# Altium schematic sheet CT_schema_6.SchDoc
size 373 x 245 mm
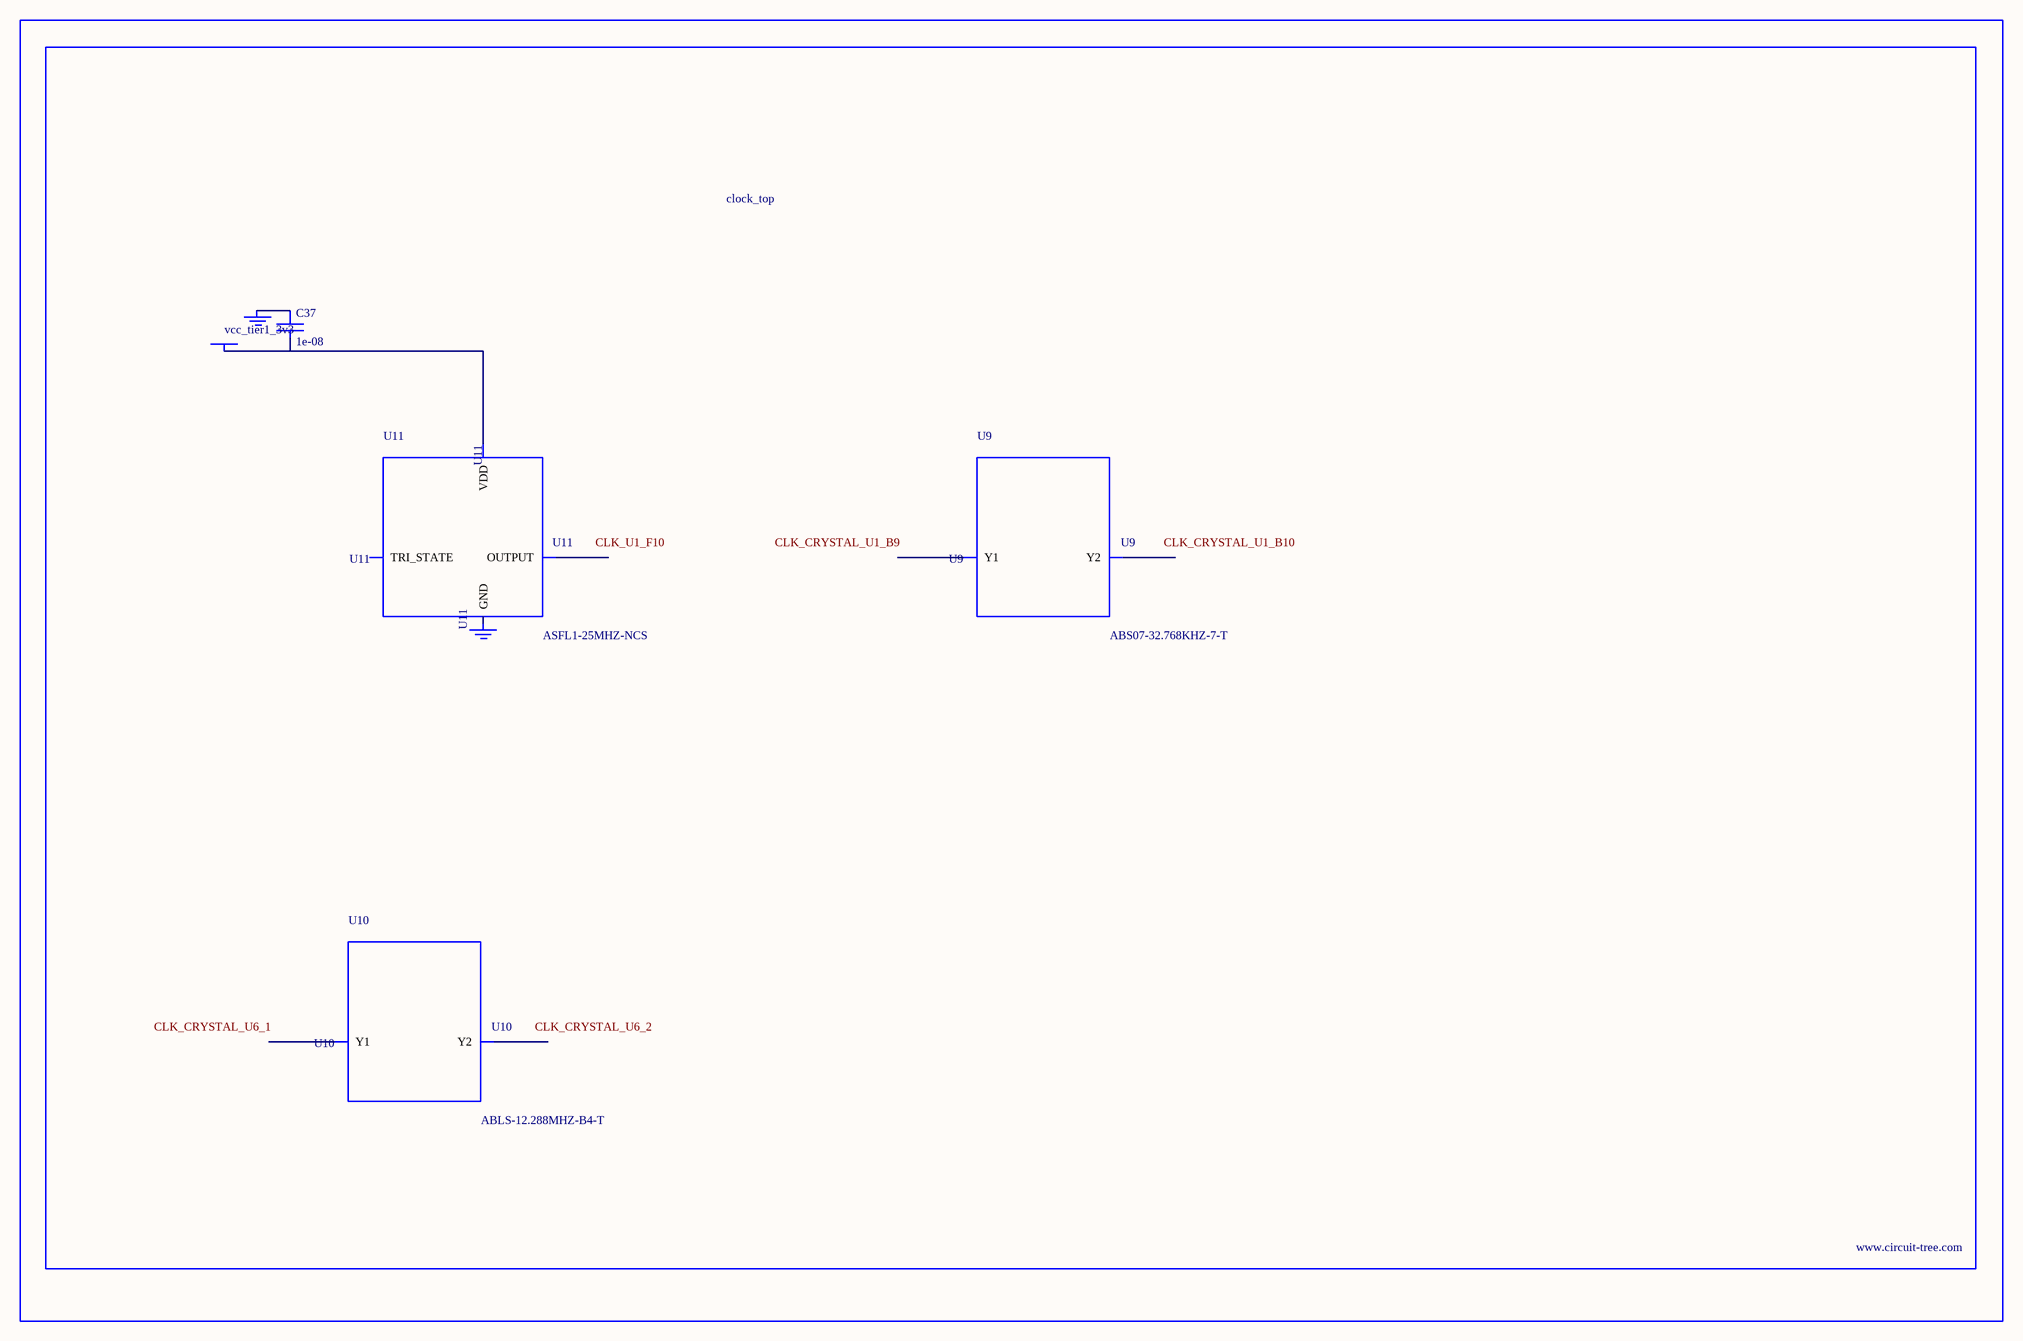
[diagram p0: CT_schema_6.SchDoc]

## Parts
BORDER5  (no value)
C37  1e-08  [C0402]
GND_INSTANCE_5_0  (no value)
GND_INSTANCE_5_1  (no value)
POWER_INSTANCE_5_0  vcc_tier1_3v3
U9  ABS07-32.768KHZ-7-T  [ABS07-32.768KHZ-7-T]
U10  ABLS-12.288MHZ-B4-T  [ABLS-12.288MHZ-B4-T]
U11  ASFL1-25MHZ-NCS  [ASFL1]

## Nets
NetC37_1: C37.1 GND_INSTANCE_5_0.0(GND)
NetC37_2: C37.2 POWER_INSTANCE_5_0.0(PWR) U11.4(VDD)

Not connected (* = marked no-connect by the designer): GND_INSTANCE_5_1 0(GND); U9 1(Y1) 2(Y2); U10 1(Y1) 2(Y2); U11 1(TRI_STATE) 2(GND) 3(OUTPUT)

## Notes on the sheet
- Labels drawn without touching a wire or pin: CLK_CRYSTAL_U1_B9, CLK_CRYSTAL_U1_B10, CLK_CRYSTAL_U6_1, CLK_CRYSTAL_U6_2, CLK_U1_F10

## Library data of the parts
BORDER5 = BORDER_PAGE5
C37 = C0402C103K3RAC
GND_INSTANCE_5_0 GND_INSTANCE_5_1 = GND
POWER_INSTANCE_5_0 = PWR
